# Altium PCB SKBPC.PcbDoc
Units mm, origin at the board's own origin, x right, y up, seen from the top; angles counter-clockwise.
Board outline 28.5 x 28.5 mm, 2 copper layers (Top Layer, Bottom Layer); 0 components, 14 nets, 6 pads, 0 vias.
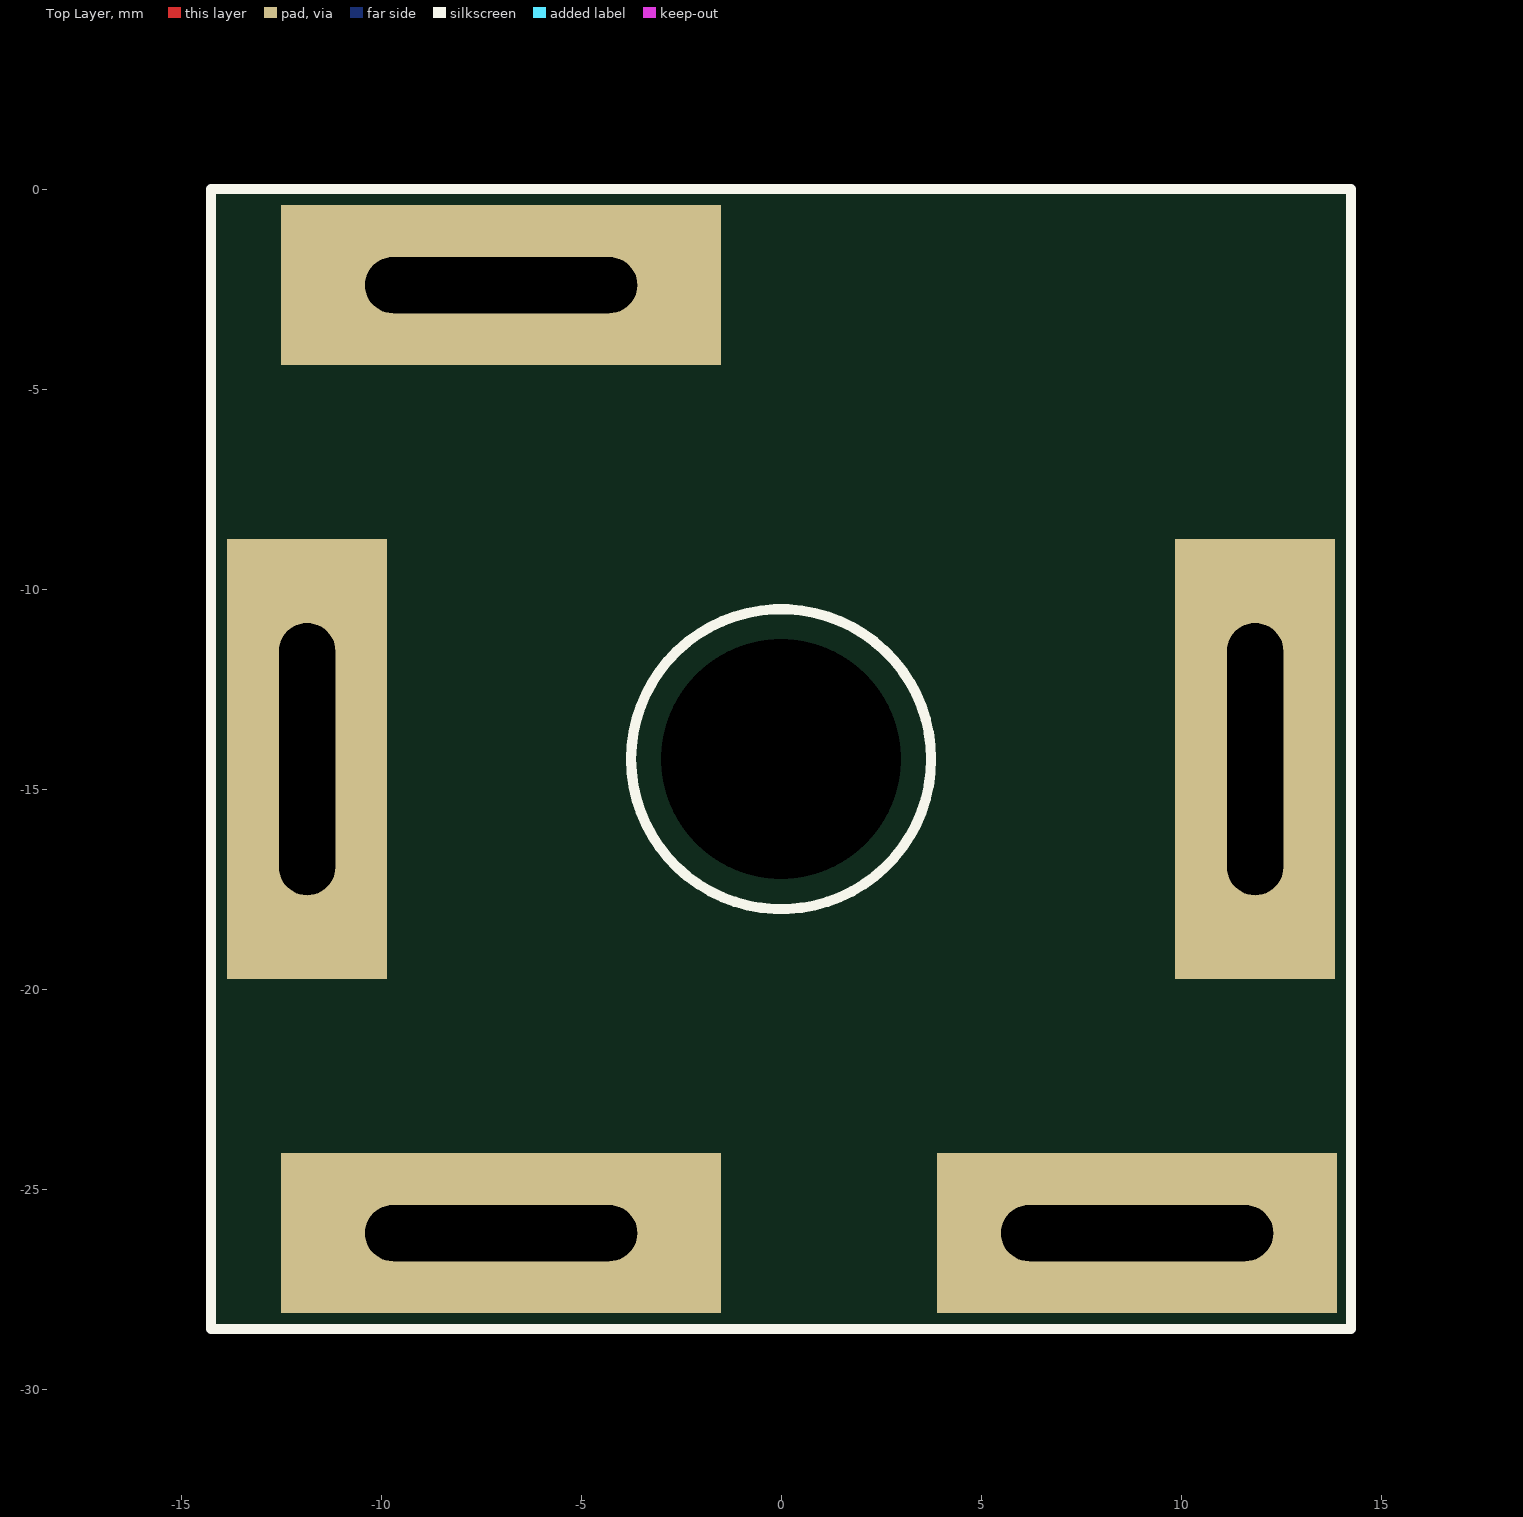
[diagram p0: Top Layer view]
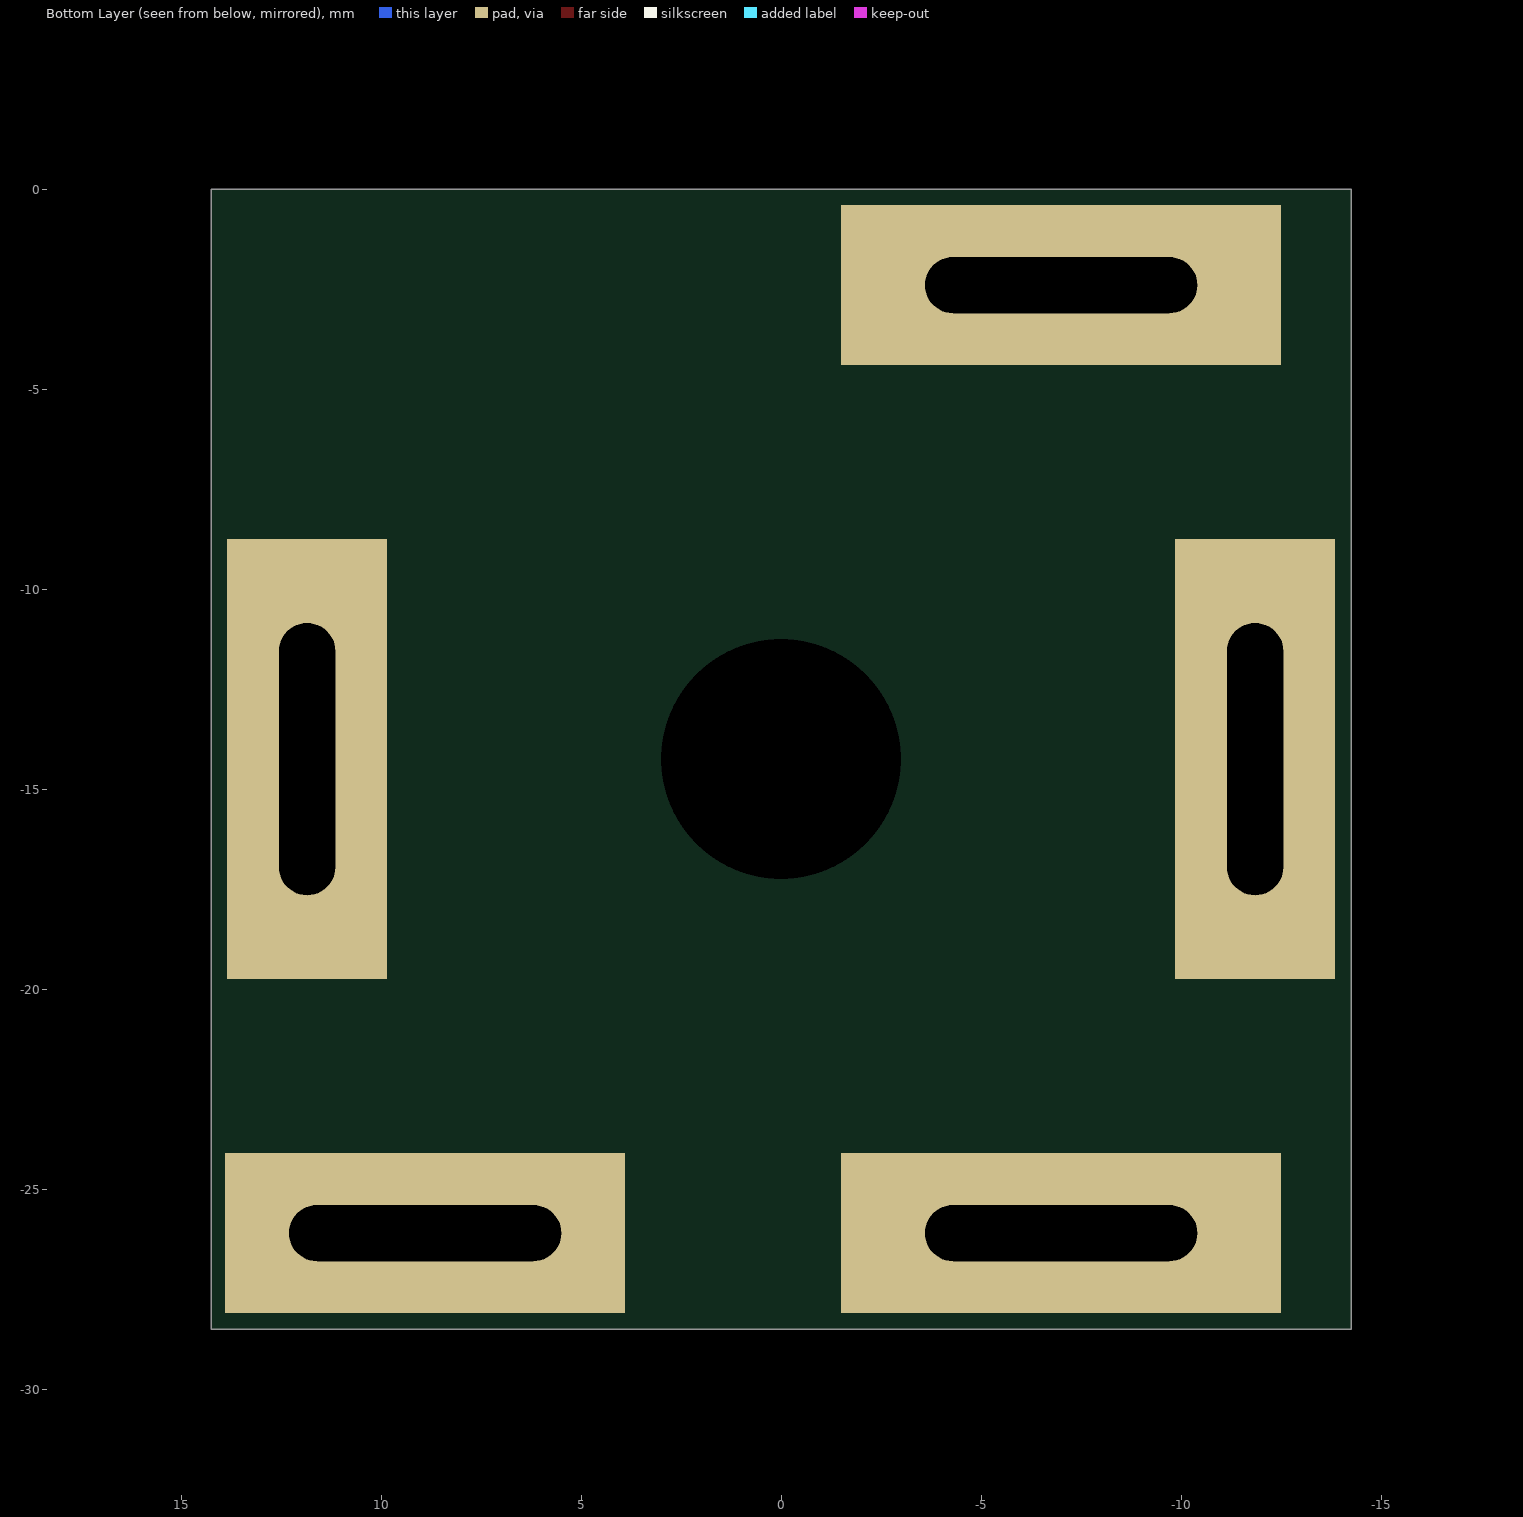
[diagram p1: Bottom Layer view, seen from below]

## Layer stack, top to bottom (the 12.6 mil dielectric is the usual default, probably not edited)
Top Layer: signal copper 0.0356
Dielectric: dielectric 0.32, FR-4, Dk 4.8
Bottom Layer: signal copper 0.0356

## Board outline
-14.25,-28.5 -14.25,0 14.25,0 14.25,-28.5

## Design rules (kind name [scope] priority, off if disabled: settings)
Clearance [All] p1: gap=0.254
PolygonConnect [All] p1: connectstyle=Relief reliefconductorwidth=0.254 reliefentries=4 polygonreliefangle="90 Angle"
RoutingVias [All] p1: holewidth=0.711 width=1.27 viastyle="Through Hole" minholewidth=0.711 minwidth=1.27 maxholewidth=0.711 maxwidth=1.27
SilkscreenOverComponentPads [All] p1: minsilkscreentomaskgap=0.254
SolderMaskExpansion [All] p1: expansion=0.102
Width [All] p1: maxlimit=3 minlimit=0.254 preferedwidth=0.254 minimp=50.000000 maximp=50.000000 favimp=50.000000
27 further rules are at their usual default settings.

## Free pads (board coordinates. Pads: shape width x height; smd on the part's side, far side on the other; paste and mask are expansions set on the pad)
  round 0 hole 6: 0(0,-14.25)
  rect 4x11 hole 1.4 slot 6.8 at 90 deg: 1(11.85,-14.25) 2(-11.85,-14.25)
  rect 10x4 hole 1.4 slot 6.8 at 0 deg: 4(8.9,-26.1)
  rect 11x4 hole 1.4 slot 6.8 at 0 deg: 5(-7,-26.1) 6(-7,-2.4)

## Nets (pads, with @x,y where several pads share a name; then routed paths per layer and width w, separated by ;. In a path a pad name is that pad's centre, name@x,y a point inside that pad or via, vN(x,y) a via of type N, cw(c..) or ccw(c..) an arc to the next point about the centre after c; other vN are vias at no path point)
GND: 
NetC3_2: 
NetC5_1: 
NetCFF_2: 
NetD1_2: 
NetL1_1: 
NetL2_2: 
NetMC2_10: 
V: 
VAUX: 
VAUX2: 
VCELL: 
VOUT: 
VOUT2: 

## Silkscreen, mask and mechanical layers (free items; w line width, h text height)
Top Overlay:
  circle w0.254: c0,-14.25 r3.75
  lines w0.254: -14.25,-28.5 14.25,-28.5 14.25,0 -14.25,0 -14.25,-28.5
